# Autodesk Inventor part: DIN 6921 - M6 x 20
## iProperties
Comments: To add or edit properties for Autodesk Inventor files, use iProperties.
Created: 2004-08
Part Number: DIN 6921 - M6 x 20
Vendor: Autodesk Inc.
Document SubType Name: Modeling
Designer: AG
Material: Standard
Description: Sechskantschraube mit Flansch
Standard: DIN 6921
Manufacturer: Standard
Standards Organization: Custom
Alert: To add or edit properties for Autodesk Inventor files, use iProperties.
Control State: 0
Master: False
Checked Out: False
Shininess: 64.0
Length Units: 11269
Angle Units: 11279
Time Units: 11290
Mass Units: 11283
Length Display Precision: 3
Angle Display Precision: 2
Compacted: True
EGR: 1
Classification: un/spsc 31161513
Density: 0.0
Volumn: 0.0
Area: 0.0
PropertySet Name: Model Information
Author: AG
Revision Number: 5
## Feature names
1. Körper [Revolution]
2. Kopf [Extrusion]
3. Fase1 [Revolution]
4. Fase2 [Chamfer]
